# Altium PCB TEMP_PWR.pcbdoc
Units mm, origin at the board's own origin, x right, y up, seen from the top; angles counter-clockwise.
Board outline 61.6 x 60 mm, 2 copper layers (Top Layer, Bottom Layer); 28 components, 19 nets, 52 pads, 21 vias.
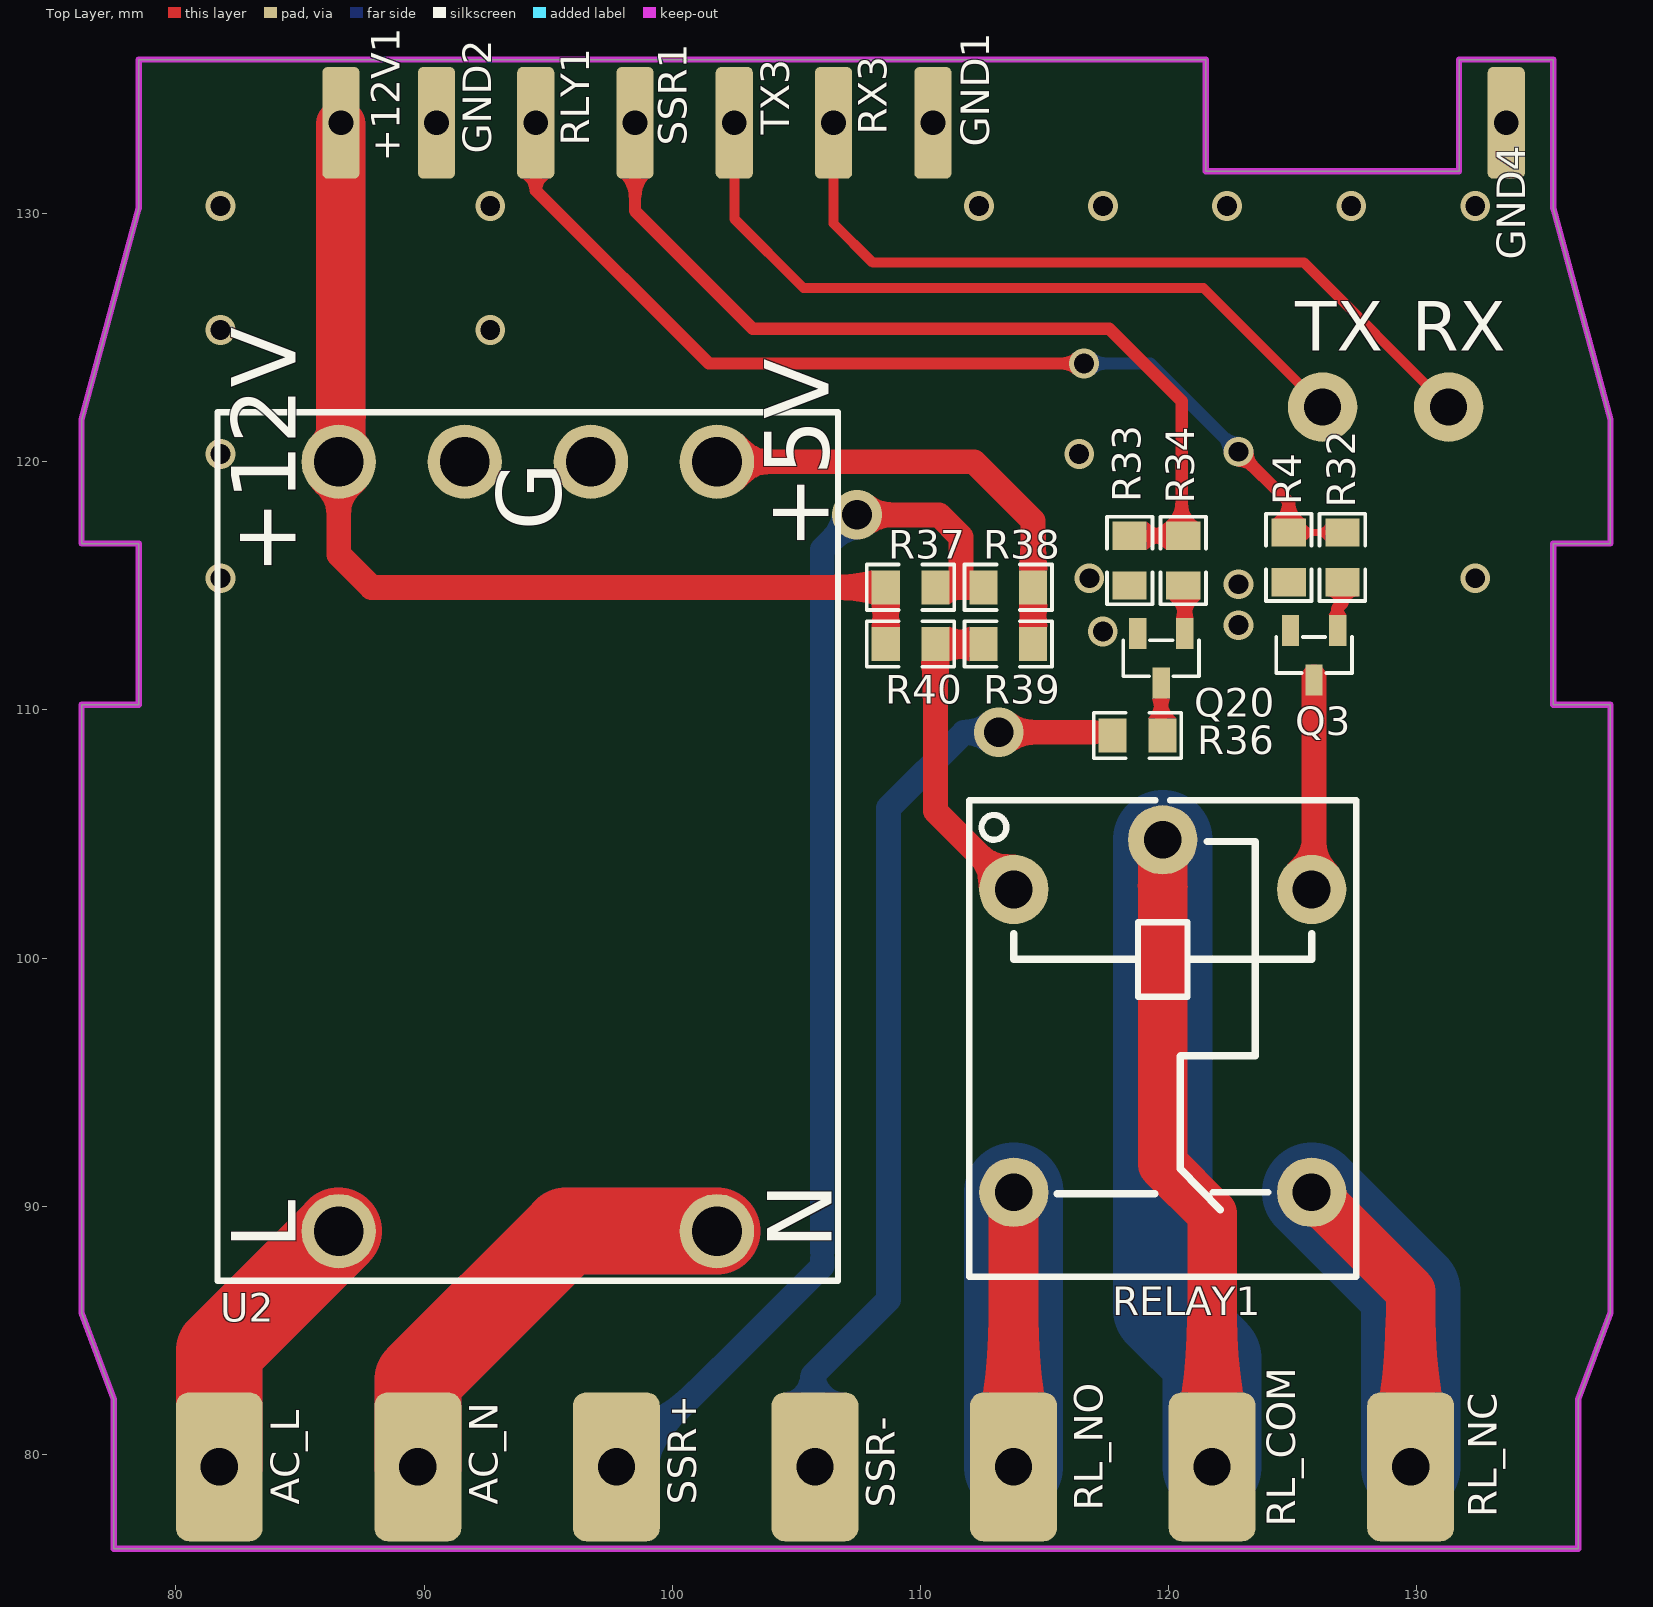
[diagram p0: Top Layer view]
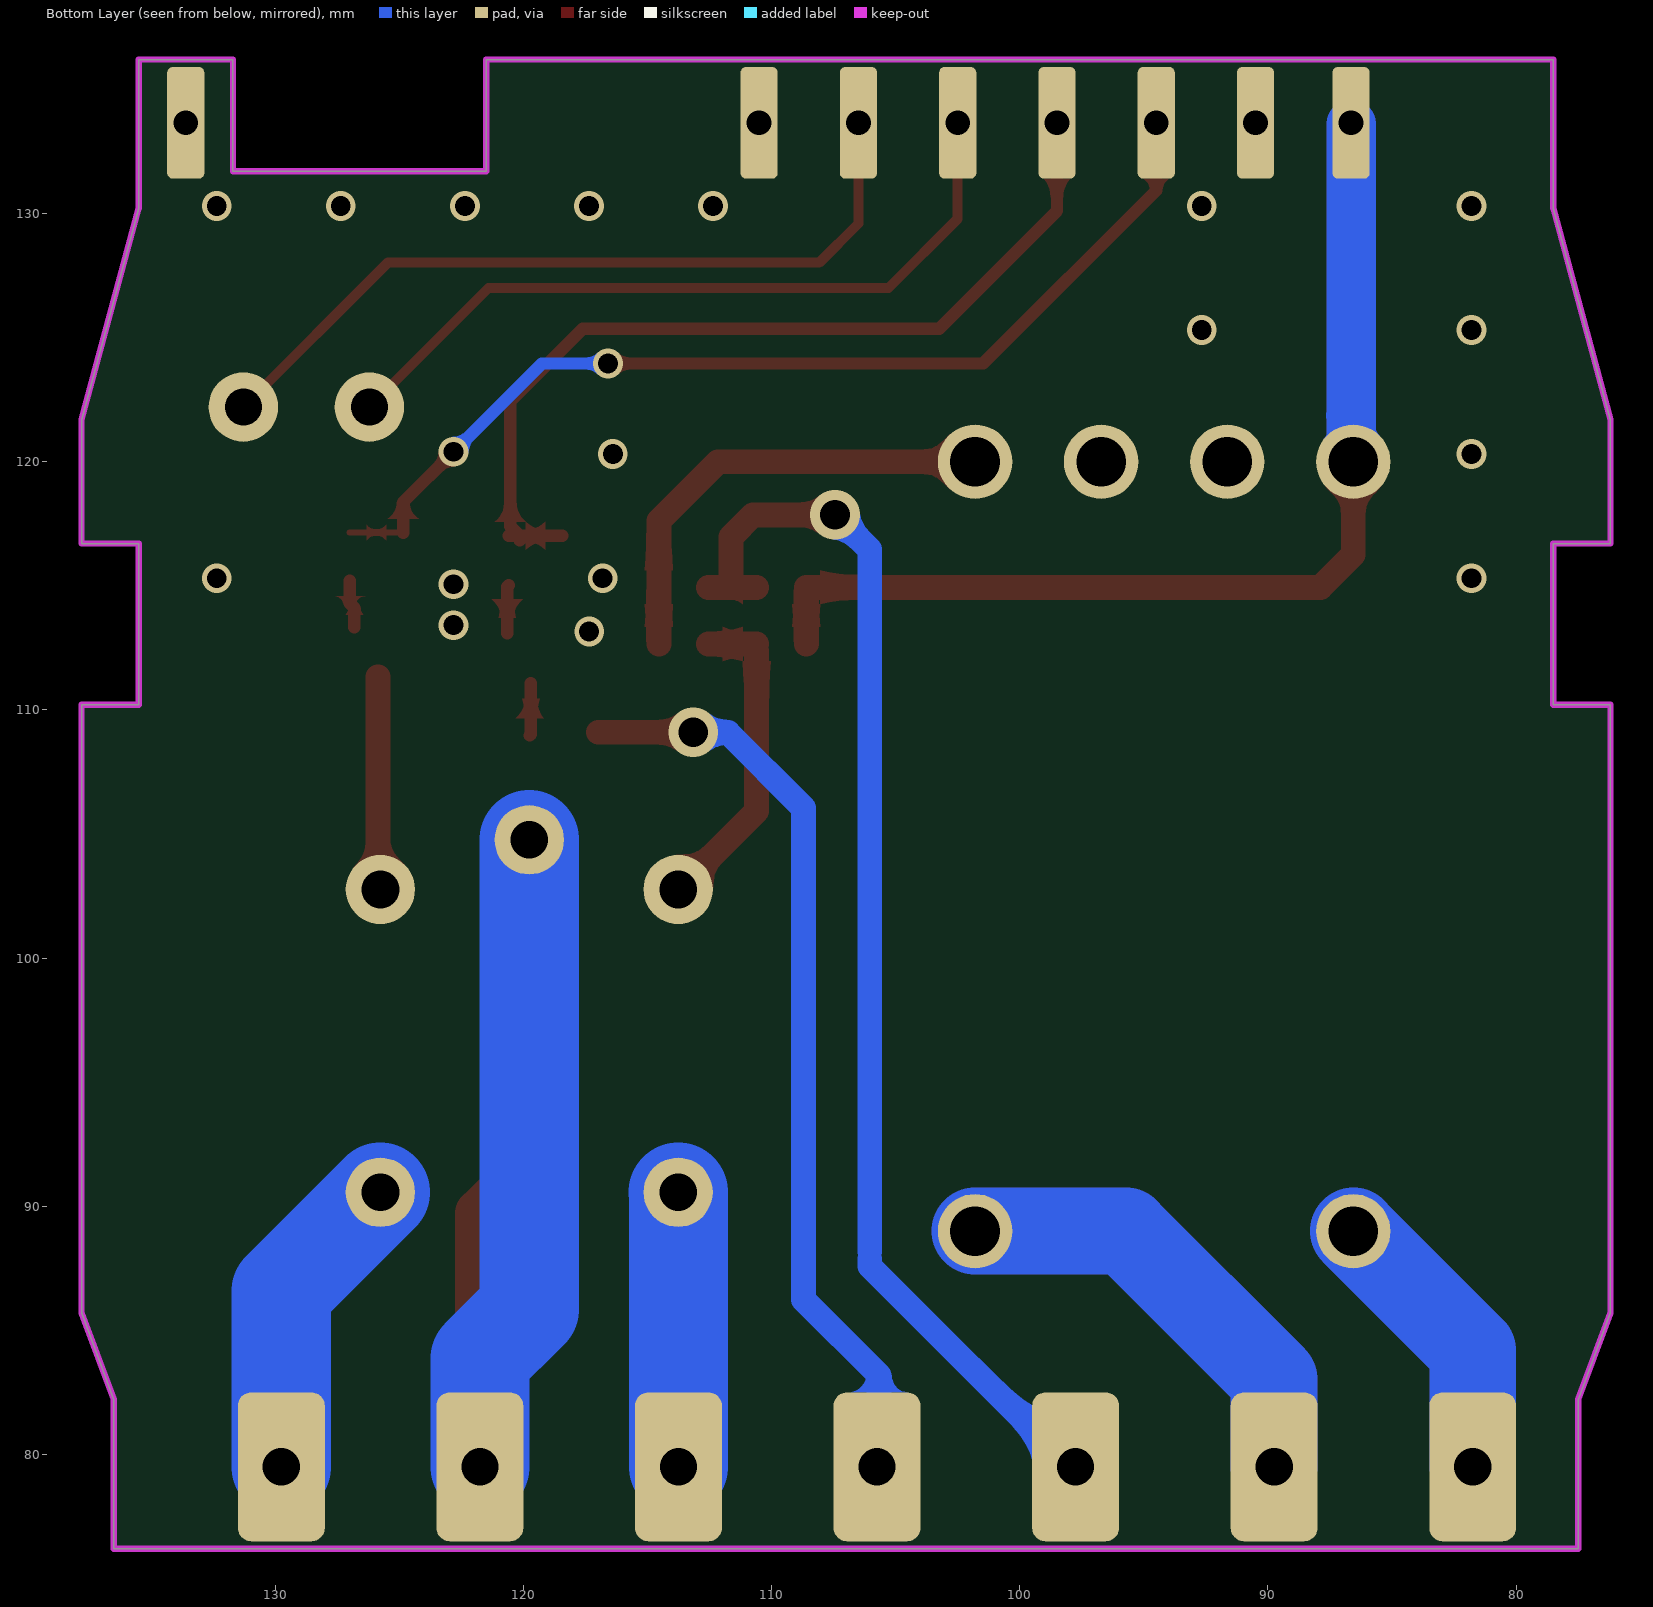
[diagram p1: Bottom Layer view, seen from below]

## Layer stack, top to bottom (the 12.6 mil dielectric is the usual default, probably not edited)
Top Layer: signal copper (thickness not stored)
Dielectric: dielectric 0.32, FR-4, Dk 4.8
Bottom Layer: signal copper (thickness not stored)

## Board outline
77.5,82.2 77.5,76.2 136.5,76.2 136.5,82.2 137.8,85.7 137.8,110.2 135.5,110.2 135.5,116.7 137.8,116.7 137.8,121.7 135.5,130.2 135.5,136.2 131.7,136.2 131.7,131.7 121.5,131.7 121.5,136.2 78.5,136.2 78.5,130.2 76.2,121.7 76.2,116.7 78.5,116.7 78.5,110.2 76.2,110.2 76.2,85.7

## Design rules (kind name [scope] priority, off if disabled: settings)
BoardOutlineClearance copperThickness1oz [All] p0: genericclearance=0.254 ignorepadtopadclearanceinfootprint=FALSE except(0: Arc-SplitContinuation Track-SplitContinuation SMDPad-SplitContinuation THPad-SplitContinuation Via-SplitContinuation Fill-SplitContinuation Poly-SplitContinuation Region-SplitContinuation Text-SplitContinuation; 0.203: Track-CutoutEdge SMDPad-CutoutEdge THPad-CutoutEdge Via-CutoutEdge Region-CutoutEdge; 0.3: Track-OutlineEdge SMDPad-OutlineEdge THPad-OutlineEdge Via-OutlineEdge Fill-OutlineEdge Region-OutlineEdge Poly-OutlineEdge Text-OutlineEdge Fill-CutoutEdge)
Clearance copperThickness1oz [(InNet('$1N452') OR InNet('GND') OR InNet('$1N448') OR InNet('$1N459') OR InNet('+12V') OR InNet('$1N1061') OR InNet('RLY') OR InNet('SSR') OR InNet('RL_NO') OR InNet('RL_COM') OR InNet('RL_NC') OR InNet('AC_L') OR InNet('AC_N') OR InNet('SSR-') OR InNet('SSR+') OR InNet('U3_RX') OR InNet('U3_TX') OR InNet('+5V') OR InNet('$1N449'))] p1: gap=0.178 ignorepadtopadclearanceinfootprint=FALSE except(0.201: SMDPad-SMDPad; 0.203: Track-Track Track-SMDPad Track-Via SMDPad-Via THPad-Via SMDPad-Fill THPad-Fill Via-Fill Fill-Fill Track-Region SMDPad-Region THPad-Region Via-Region Region-Region Track-Poly SMDPad-Poly THPad-Poly Via-Poly Fill-Poly Region-Poly Poly-Poly Track-Text SMDPad-Text THPad-Text Via-Text Fill-Text Region-Text Poly-Text Text-Text Track-Hole SMDPad-Hole THPad-Hole Via-Hole Fill-Hole Region-Hole Poly-Hole Text-Hole Sheet-Hole; 0.254: Track-THPad SMDPad-THPad THPad-THPad; 0.3: Track-Fill Fill-Region Track-Sheet SMDPad-Sheet THPad-Sheet Via-Sheet Fill-Sheet Region-Sheet Poly-Sheet Text-Sheet; 0.305: Via-Via)
DiffPairsRouting differentialPair [All] p1: maxuncoupledlength=10 minlimit=5.9843 maxlimit=5.9843 mostfreqgap=5.9843 toplayer_minwidth=5 toplayer_prefwidth=10 toplayer_maxwidth=100 bottomlayer_minwidth=5 bottomlayer_prefwidth=10 bottomlayer_maxwidth=100
PasteMaskExpansion pasteMaskExpansion [All] p1: expansion=0
PlaneConnect innerPlane [All] p1: planeconnectstyle=Relief reliefexpansion=0.508 reliefentries=4 reliefconductorwidth=0.254 reliefairgap=0.254
PolygonConnect copperRegion [All] p1: connectstyle=Direct reliefentries=4 reliefconductorwidth=10 polygonreliefangle="90 Angle" airgapwidth=10
RoutingVias viaSize [All] p1: viastyle="Through Hole" holewidth=19.685 minholewidth=19.685 maxholewidth=393.7008 width=31.496 minwidth=19.685 maxwidth=393.7008
SolderMaskExpansion solderMaskExpansion [All] p1: useseparateexpansions=TRUE expansion=2.0079 expansionbottom=2.0079
Width copperThickness1oz [All] p1: maxlimit=197 minlimit=5 preferedwidth=10
Width copperThickness2oz [All] p1: maxlimit=100 minlimit=8 preferedwidth=10

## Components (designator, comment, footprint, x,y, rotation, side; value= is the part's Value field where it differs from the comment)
+12V1 "S_TM" S_FT 86.65,133.65 r180 top
AC_L "B_TM" B_FT 81.75,79.5 r0 top
AC_N "B_TM" B_FT 89.75,79.5 r0 top
GND1 "S_TM" S_FT 110.5,133.65 r180 top
GND2 "S_TM" S_FT 90.5,133.65 r180 top
GND4 "S_TM" S_FT 133.6,133.65 r0 top
Q3 "AO3400A_C347475" SOT-23-3_L2.9-W1.3-P1.90-LS2.4-BR 125.857,112.204 r90 top
Q20 "AO3400A_C347475" SOT-23-3_L2.9-W1.3-P1.90-LS2.4-BR 119.697,112.078 r90 top
R4 "RC0805FR-0710KL" R0805 124.841,116.141 r90 top
R32 "RC0805FR-071KL" R0805 127,116.141 r90 top
R33 "RC0805FR-0710KL" R0805 118.427,116.014 r90 top
R34 "RC0805FR-071KL" R0805 120.587,116.014 r90 top
R36 "RC0805JR-070RL" R0805 118.745,108.966 r180 top
R37 "RC0805JR-070RL" R0805 109.601,114.935 r180 top
R38 "RC0805JR-070RL" R0805 113.538,114.935 r0 top
R39 "RC0805JR-070RL" R0805 113.538,112.649 r0 top
R40 "RC0805JR-070RL" R0805 109.601,112.649 r180 top
RELAY1 "SRD-12VDC-SL-C" RELAY-TH_SRD-XXVDC-XL-C 119.761,97.663 r270 top
RL_COM "B_TM" B_FT 121.75,79.5 r0 top
RL_NC "B_TM" B_FT 129.75,79.5 r0 top
RL_NO "B_TM" B_FT 113.75,79.5 r0 top
RLY1 "S_TM" S_FT 94.5,133.65 r180 top
RX3 "S_TM" S_FT 106.5,133.65 r180 top
SSR1 "S_TM" S_FT 98.5,133.65 r180 top
SSR+ "B_TM" B_FT 97.75,79.5 r0 top
SSR- "B_TM" B_FT 105.75,79.5 r0 top
TX3 "S_TM" S_FT 102.5,133.65 r180 top
U2 "P_12V5V_MOD" P_MOD1 106.68,86.995 r90 top

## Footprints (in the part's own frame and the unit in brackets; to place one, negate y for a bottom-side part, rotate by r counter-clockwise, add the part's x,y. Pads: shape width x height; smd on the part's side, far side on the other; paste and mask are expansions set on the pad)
B_FT [mm]
  rrect30% 3.5x6 hole 1.5: 1(0,0)
P_MOD1 [mm]
  round 3 hole 2: 1(2,20.12) 2(2,4.88) 3(33,4.88) 4(33,9.96) 5(33,15.04) 6(33,20.12)
  silkscreen extent 0,0 35,25
R0805 [mm]
  rect 1.133x1.377 smd: 1(-1,0) 2(1,0)
  silkscreen extent -1.76,-0.92 1.76,0.92
RELAY-TH_SRD-XXVDC-XL-C [mil]
  round 110 hole 60: 1(-200.79,-236.22) 2(279.53,-236.2) 3(279.53,236.2) 4(-200.79,236.22) 5(-279.53,0)
  silkscreen extent -342,-307 413,307
S_FT [mm]
  rrect30% 1.5x4.5 hole 1: 1(0,0)
SOT-23-3_L2.9-W1.3-P1.90-LS2.4-BR [mm]
  rect 1.25x0.7 smd: 1(1,-0.95) 2(1,0.95) 3(-1,0)
  silkscreen extent -0.73,-1.53 0.73,1.53

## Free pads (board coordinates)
  round 2.8 hole 1.5: 1(126.2,122.2) 2(131.28,122.2)

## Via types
v1: diameter 1.2, hole 0.8, Top Layer to Bottom Layer, 19 vias
v2: diameter 2, hole 1.2, Top Layer to Bottom Layer, 2 vias

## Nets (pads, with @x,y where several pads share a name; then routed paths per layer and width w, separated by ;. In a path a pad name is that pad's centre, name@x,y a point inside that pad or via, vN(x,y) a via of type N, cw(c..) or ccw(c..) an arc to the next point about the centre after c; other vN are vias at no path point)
$1N448: Q3.3 RELAY1.4 | length 8.6
  Top Layer w1: RELAY1.4 125.857,102.859 Q3.3@125.857,111.332
$1N449: R39.1 R40.1 RELAY1.1 | length 13.2
  Top Layer w1: R40.1 R40.1@110.876,112.649 ; R39.1 R40.1@110.876,112.649 ; RELAY1.1 110.601,105.923 110.601,112.374 R40.1@110.876,112.649
$1N452: Q3.1 R32.1 | length 2
  Top Layer w0.5: Q3.1@126.807,113.331 126.807,114.107 127,114.3 R32.1@127,115.205
$1N459: Q20.1 R34.1 | length 2
  Top Layer w0.5: R34.1 120.647,114.954 Q20.1
$1N1061: Q20.3 R36.1 | length 2.1
  Top Layer w0.5: Q20.3 119.697,109.013 R36.1
+5V: R38.2 R39.2 U2.3 | length 18.7
  Top Layer w1: U2.3 112.161,119.995 114.538,117.618 R38.2 R39.2
+12V: +12V1.1 R37.2 R40.2 U2.6 | length 55.9
  Top Layer w1: U2.6 86.56,116.259 87.884,114.935 R37.2 R40.2 R40.2@108.585,112.665
  Top Layer w2: U2.6 86.65,120.085 +12V1.1@86.65,133.6
  Bottom Layer w2: U2.6 86.65,120.085 +12V1.1@86.65,133.6
AC_L: AC_L.1 U2.1 | length 23
  Top Layer w3.5: AC_L.1 81.75,84.185 U2.1
  Bottom Layer w3.5: AC_L.1 81.75,84.185 U2.1
AC_N: AC_N.1 U2.2 | length 36.1
  Top Layer w3.5: AC_N.1 89.75,83.019 95.726,88.995 U2.2
  Bottom Layer w3.5: AC_N.1 89.75,83.019 95.726,88.995 U2.2
GND: GND1.1 GND2.1 GND4.1 Q3.2 Q20.2 R4.1 R33.1 U2.4 U2.5
  other v1: 117.348,113.157 122.809,113.411 122.809,115.062 81.804,115.302 116.804,115.302 132.354,115.302 81.804,120.302 116.394,120.302 81.804,125.302 92.664,125.302 81.804,130.302 92.664,130.302 112.354,130.302 117.354,130.302 122.354,130.302 127.354,130.302 132.354,130.302
RL_COM: RELAY1.5 RL_COM.1 | length 52.2
  Top Layer w2: RELAY1.5 119.761,91.694 121.75,89.705 RL_COM.1
  Bottom Layer w4: RELAY1.5 119.761,85.852 121.75,83.863 RL_COM.1
RL_NC: RELAY1.3 RL_NC.1 | length 25.4
  Top Layer w2: RELAY1.3 129.75,86.573 RL_NC.1
  Bottom Layer w4: RELAY1.3 129.75,86.573 RL_NC.1
RL_NO: RELAY1.2 RL_NO.1 | length 22.1
  Top Layer w2: RL_NO.1 113.75,90.551 RELAY1.2
  Bottom Layer w4: RL_NO.1 113.75,90.551 RELAY1.2
RLY: R4.2 R32.2 RLY1.1 | length 41.7
  Top Layer w0.254: R4.2 R32.2
  Top Layer w0.5: RLY1.1 94.5,130.925 101.473,123.952 v1(116.586,123.952) ; v1(122.809,120.396) 124.841,118.364 R4.2
  Bottom Layer w0.5: v1(116.586,123.952) 119.253,123.952 v1(122.809,120.396)
SSR: R33.2 R34.2 SSR1.1 | length 36.7
  Top Layer w0.5: SSR1.1 98.5,130.1 103.251,125.349 117.609,125.349 120.523,122.435 120.523,117.395 R34.2@120.142,117.014 ; R33.2 R34.2@120.142,117.014 ; R34.2@120.142,116.824 R34.2@120.142,117.014 ; R34.2 R34.2@120.142,117.014
SSR+: R37.1 R38.1 SSR+.1 | length 50.7
  Top Layer w1: v2(107.442,117.856) 110.744,117.856 111.633,116.967 111.633,114.935 ; R37.1 111.633,114.935 ; R38.1 111.633,114.935
  Bottom Layer w1: SSR+.1 97.959,79.5 106.045,87.586 106.045,87.884 ; 106.045,88.176 106.045,116.459 v2(107.442,117.856)
SSR-: R36.2 SSR-.1 | length 37.4
  Top Layer w1: v2(113.157,109.093) 116.983,109.093
  Bottom Layer w1: SSR-.1 105.664,79.586 105.664,83.185 108.712,86.233 108.712,106.045 111.76,109.093 v2(113.157,109.093)
U3_RX: pad.2 RX3.1 | length 31.9
  Top Layer w0.4: RX3.1 106.5,129.593 108.077,128.016 125.464,128.016 pad.2
U3_TX: pad.1 TX3.1 | length 30.7
  Top Layer w0.4: TX3.1 102.5,129.783 105.283,127 121.4,127 pad.1

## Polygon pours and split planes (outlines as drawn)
GND on Top Layer (solid, remove dead copper, pour order 0): 76.2,121.7 76.2,116.7 78.5,116.7 78.5,110.2 135.5,110.2 135.5,116.7 137.8,116.7 137.8,121.7 135.5,130.2 135.5,136.2 131.7,136.2 131.7,131.7 121.5,131.7 121.5,136.2 78.5,136.2 78.5,130.2
GND on Bottom Layer (solid, remove dead copper, pour order 2): 76.2,121.7 76.2,116.7 78.5,116.7 78.5,110.2 135.5,110.2 135.5,116.7 137.8,116.7 137.8,121.7 135.5,130.2 135.5,136.2 131.7,136.2 131.7,131.7 121.5,131.7 121.5,136.2 78.5,136.2 78.5,130.2

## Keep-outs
Board Outline Layer:
  the board outline again, w0.254

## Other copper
Top Layer:
  region net $1N452: 126.557,114.107 127.057,114.107 ccw(c127.492,114.107) 127.157,113.83 126.457,113.83 ccw(c126.122,114.107)
  region net $1N459: 120.397,114.453 120.897,114.453 ccw(c123.76,114.453) 120.997,113.703 120.297,113.703 ccw(c117.535,114.453)
  region net $1N1061: 119.947,109.702 119.448,109.702 ccw(c116.585,109.702) 119.348,110.452 120.047,110.452 ccw(c122.81,109.702)
  region net RLY: 124.591,118.364 125.091,118.364 ccw(c125.853,118.364) 125.466,117.708 124.216,117.708 ccw(c123.829,118.364)
  region net RLY: 125.911,117.268 125.911,117.014 ccw(c125.911,116.538) 125.53,116.824 125.53,117.459 ccw(c125.911,117.745)
  region net RLY: 125.93,117.014 125.93,117.268 ccw(c125.93,117.745) 126.311,117.459 126.311,116.824 ccw(c125.93,116.538)
  region net $1N452: 127.25,114.3 126.75,114.3 ccw(c126.375,114.182) 126.375,114.575 127.625,114.575 ccw(c127.625,114.182)
  region net SSR: 119.866,117.264 119.866,116.764 ccw(c119.866,115.717) 119.116,116.448 119.116,117.581 ccw(c119.866,118.312)
  region net SSR: 119.148,116.764 119.148,117.264 ccw(c119.148,118.312) 119.898,117.581 119.898,116.448 ccw(c119.148,115.717)
  region net SSR: 120.273,118.331 120.773,118.331 ccw(c121.71,118.331) 121.148,117.581 119.898,117.581 ccw(c119.336,118.331)
  region net $1N459: 120.897,113.698 120.397,113.698 ccw(c119.46,113.698) 120.022,114.448 121.272,114.448 ccw(c121.835,113.698)
  region net RL_NO: 114.75,88.652 112.75,88.67 112.753,88.753 112.761,88.83 112.786,88.969 112.816,89.091 112.842,89.201 112.85,89.254 112.854,89.306 112.851,89.359 112.841,89.412 112.823,89.467 112.795,89.524 112.757,89.584 112.706,89.648 114.802,89.63 114.75,89.568 114.711,89.509 114.683,89.452 114.664,89.398 114.654,89.344 114.65,89.292 114.653,89.239 114.661,89.185 114.685,89.074 114.715,88.951 114.74,88.812 114.747,88.735
  region net RL_COM: 120.761,102.861 118.761,102.861 118.764,102.944 118.771,103.022 118.797,103.16 118.826,103.282 118.852,103.393 118.86,103.447 118.863,103.499 118.86,103.552 118.85,103.605 118.831,103.66 118.803,103.717 118.764,103.776 118.713,103.839 120.809,103.839 120.758,103.776 120.719,103.717 120.691,103.66 120.672,103.605 120.662,103.552 120.659,103.499 120.662,103.447 120.67,103.393 120.696,103.282 120.725,103.16 120.751,103.022 120.758,102.944
  region net $1N448: 125.357,104.735 126.357,104.591 126.36,104.514 126.369,104.441 126.382,104.373 126.401,104.307 126.424,104.245 126.452,104.184 126.483,104.126 126.517,104.069 126.595,103.958 126.681,103.848 126.87,103.613 124.779,103.757 124.887,103.864 124.991,103.973 125.089,104.085 125.176,104.201 125.215,104.261 125.25,104.322 125.281,104.386 125.307,104.451 125.328,104.518 125.344,104.588 125.354,104.66
  region net $1N449: 112.063,103.754 112.77,104.461 112.826,104.41 112.883,104.365 112.943,104.327 113.004,104.294 113.066,104.266 113.131,104.243 113.197,104.225 113.264,104.209 113.403,104.188 113.547,104.175 113.848,104.157 112.367,102.676 112.349,102.977 112.336,103.121 112.315,103.26 112.3,103.327 112.281,103.393 112.258,103.458 112.23,103.52 112.197,103.582 112.159,103.641 112.114,103.699
  region net RL_NC: 127.812,89.925 126.398,88.511 126.341,88.572 126.292,88.632 126.212,88.747 126.147,88.855 126.086,88.951 126.054,88.995 126.019,89.034 125.98,89.069 125.935,89.1 125.883,89.125 125.823,89.146 125.754,89.16 125.673,89.169 127.155,90.65 127.163,90.57 127.178,90.5 127.198,90.44 127.224,90.389 127.254,90.344 127.289,90.304 127.329,90.269 127.372,90.237 127.468,90.177 127.576,90.111 127.692,90.031 127.752,89.982
  region net $1N1061: 119.448,110.405 119.947,110.405 ccw(c120.903,110.405) 120.311,109.655 119.179,109.655 ccw(c118.267,110.405)
  region net +12V: 109.101,112.746 108.101,112.746 ccw(c91.091,112.746) 108.035,114.246 109.167,114.246 ccw(c126.111,112.746) 109.101,112.746
  region net +12V: 106.535,114.435 106.535,115.435 ccw(c106.535,121.497) 108.035,115.624 108.035,114.246 ccw(c106.535,108.373)
  region net SSR+: 111.633,115.435 111.633,114.435 ccw(c111.633,113.765) 111.167,114.246 111.167,115.624 ccw(c111.633,116.105)
  region net RLY: 94.75,130.925 94.25,130.925 ccw(c93.702,130.925) 93.975,131.4 95.025,131.4 ccw(c95.298,130.925)
  region net RL_COM: 120.75,85.5 122.75,85.5 ccw(c142.863,85.5) 122.975,82.5 120.525,82.5 ccw(c100.637,85.5) 120.75,85.5
  region net RL_NC: 128.75,85.5 130.75,85.5 ccw(c150.863,85.5) 130.975,82.5 128.525,82.5 ccw(c108.637,85.5)
  region net RL_NO: 112.75,85.5 114.75,85.5 ccw(c134.863,85.5) 114.975,82.5 112.525,82.5 ccw(c92.637,85.5) 112.75,85.5
  region net SSR: 98.75,130.65 98.25,130.65 ccw(c97.09,130.65) 97.975,131.4 99.025,131.4 ccw(c99.91,130.65)
  region net +5V: 114.038,117.124 115.038,117.124 ccw(c132.048,117.123) 115.104,115.624 113.972,115.624 ccw(c97.028,117.124) 114.038,117.124
  region net +5V: 115.038,112.746 114.038,112.746 ccw(c97.028,112.746) 113.972,114.246 115.104,114.246 ccw(c132.048,112.747) 115.038,112.746
  region net +5V: 114.038,114.838 115.038,114.838 ccw(c132.048,114.837) 115.104,113.338 113.972,113.338 ccw(c97.028,114.838) 114.038,114.838
  region net $1N449: 110.876,112.149 110.876,113.149 ccw(c110.876,116.426) 111.972,113.338 111.972,111.96 ccw(c110.876,108.872)
  region net +5V: 103.842,120.495 103.842,119.495 103.756,119.491 103.676,119.481 103.6,119.464 103.529,119.441 103.461,119.413 103.396,119.38 103.333,119.342 103.273,119.3 103.156,119.205 103.039,119.099 102.92,118.987 102.792,118.87 102.792,121.12 102.92,121.003 103.039,120.891 103.156,120.785 103.273,120.69 103.333,120.648 103.396,120.61 103.461,120.577 103.529,120.549 103.6,120.526 103.676,120.509 103.756,120.499
  region net +12V: 87.06,117.953 86.06,117.953 86.056,118.039 86.046,118.119 86.029,118.195 86.006,118.266 85.978,118.334 85.945,118.399 85.907,118.462 85.865,118.522 85.77,118.639 85.664,118.756 85.552,118.875 85.435,119.003 87.685,119.003 87.568,118.875 87.456,118.756 87.35,118.639 87.255,118.522 87.213,118.462 87.175,118.399 87.142,118.334 87.114,118.266 87.091,118.195 87.074,118.119 87.064,118.039
  region net +12V: 85.65,122.103 87.65,121.968 87.648,121.883 87.642,121.804 87.624,121.659 87.604,121.528 87.589,121.406 87.586,121.347 87.587,121.289 87.594,121.23 87.607,121.171 87.628,121.111 87.656,121.049 87.694,120.985 87.743,120.918 85.497,121.053 85.55,121.112 85.594,121.171 85.628,121.229 85.654,121.288 85.672,121.347 85.684,121.407 85.69,121.467 85.692,121.529 85.685,121.658 85.67,121.795 85.656,121.942
  region net +12V: 108.101,114.838 109.101,114.838 ccw(c126.111,114.838) 109.167,113.338 108.035,113.338 ccw(c91.091,114.838)
  region net $1N449: 112.538,113.149 112.538,112.149 ccw(c112.538,107.071) 111.167,111.96 111.167,113.338 ccw(c112.538,118.227)
  region net $1N449: 111.101,110.46 110.101,110.46 ccw(c93.091,110.46) 110.035,111.96 111.167,111.96 ccw(c128.111,110.46)
  region net RLY: 115.769,123.702 115.769,124.202 115.826,124.206 115.883,124.219 115.939,124.239 115.993,124.264 116.046,124.295 116.097,124.329 116.189,124.402 116.189,123.502 116.097,123.575 116.046,123.609 115.993,123.64 115.939,123.665 115.883,123.685 115.826,123.698
  region net RLY: 123.563,119.995 123.21,119.642 123.166,119.679 123.117,119.71 123.064,119.735 123.007,119.756 122.948,119.772 122.889,119.784 122.771,119.797 123.408,120.434 123.421,120.316 123.433,120.257 123.449,120.198 123.47,120.141 123.495,120.088 123.526,120.039
  region net SSR-: 114.518,109.593 114.518,108.593 114.435,108.588 114.343,108.573 114.247,108.55 114.149,108.52 114.054,108.483 113.964,108.44 113.885,108.393 113.818,108.343 113.818,109.843 113.885,109.793 113.964,109.746 114.054,109.703 114.149,109.666 114.247,109.636 114.343,109.613 114.435,109.598
  region net SSR+: 108.803,118.356 108.803,117.356 108.72,117.351 108.628,117.336 108.532,117.313 108.434,117.283 108.339,117.246 108.249,117.203 108.17,117.156 108.103,117.106 108.103,118.606 108.17,118.556 108.249,118.509 108.339,118.466 108.434,118.429 108.532,118.399 108.628,118.376 108.72,118.361
Bottom Layer:
  region net SSR+: 100.674,82.922 100.289,81.124 ccw(c102.497,78.916) 99.5,79.791 99.5,81.975 ccw(c95.649,87.948)
  region net SSR-: 105.164,83.185 106.164,83.185 ccw(c106.914,83.253) 106.914,82.5 104.525,82.5 ccw(c104.477,83.185)
  region net +12V: 85.65,122.103 87.65,121.968 87.648,121.883 87.642,121.804 87.624,121.659 87.604,121.528 87.589,121.406 87.586,121.347 87.587,121.289 87.594,121.23 87.607,121.171 87.628,121.111 87.656,121.049 87.694,120.985 87.743,120.918 85.497,121.053 85.55,121.112 85.594,121.171 85.628,121.229 85.654,121.288 85.672,121.347 85.684,121.407 85.69,121.467 85.692,121.529 85.685,121.658 85.67,121.795 85.656,121.942
  region net RLY: 117.403,124.202 117.403,123.702 117.346,123.698 117.289,123.685 117.233,123.665 117.179,123.64 117.126,123.609 117.075,123.575 116.983,123.502 116.983,124.402 117.075,124.329 117.126,124.295 117.179,124.264 117.233,124.239 117.289,124.219 117.346,124.206
  region net RLY: 122.055,120.797 122.408,121.15 122.452,121.113 122.501,121.082 122.554,121.057 122.611,121.036 122.67,121.02 122.729,121.008 122.847,120.995 122.21,120.358 122.197,120.476 122.185,120.535 122.169,120.594 122.148,120.651 122.123,120.704 122.092,120.753
  region net SSR-: 111.796,108.593 111.796,109.593 111.879,109.598 111.971,109.613 112.067,109.636 112.165,109.666 112.26,109.703 112.35,109.746 112.429,109.793 112.496,109.843 112.496,108.343 112.429,108.393 112.35,108.44 112.26,108.483 112.165,108.52 112.067,108.55 111.971,108.573 111.879,108.588
  region net SSR+: 106.833,116.54 106.126,117.247 106.181,117.309 106.236,117.385 106.288,117.469 106.335,117.56 106.376,117.654 106.409,117.747 106.433,117.836 106.444,117.919 107.505,116.858 107.422,116.847 107.333,116.823 107.24,116.79 107.146,116.749 107.055,116.702 106.971,116.65 106.895,116.595

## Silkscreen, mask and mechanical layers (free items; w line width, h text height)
Top Silkscreen Layer:
  text "TX" at 125.095,124.46 h2
  text "RX" at 129.794,124.46 h2
Bottom Solder Mask Layer:
  lines w3: 113.75,79.5 113.762,79.512 113.762,90.563 ; 119.761,104.763 119.761,85.852 121.75,83.863 121.75,79.5 ; 125.76,90.563 129.75,86.573 129.75,79.5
